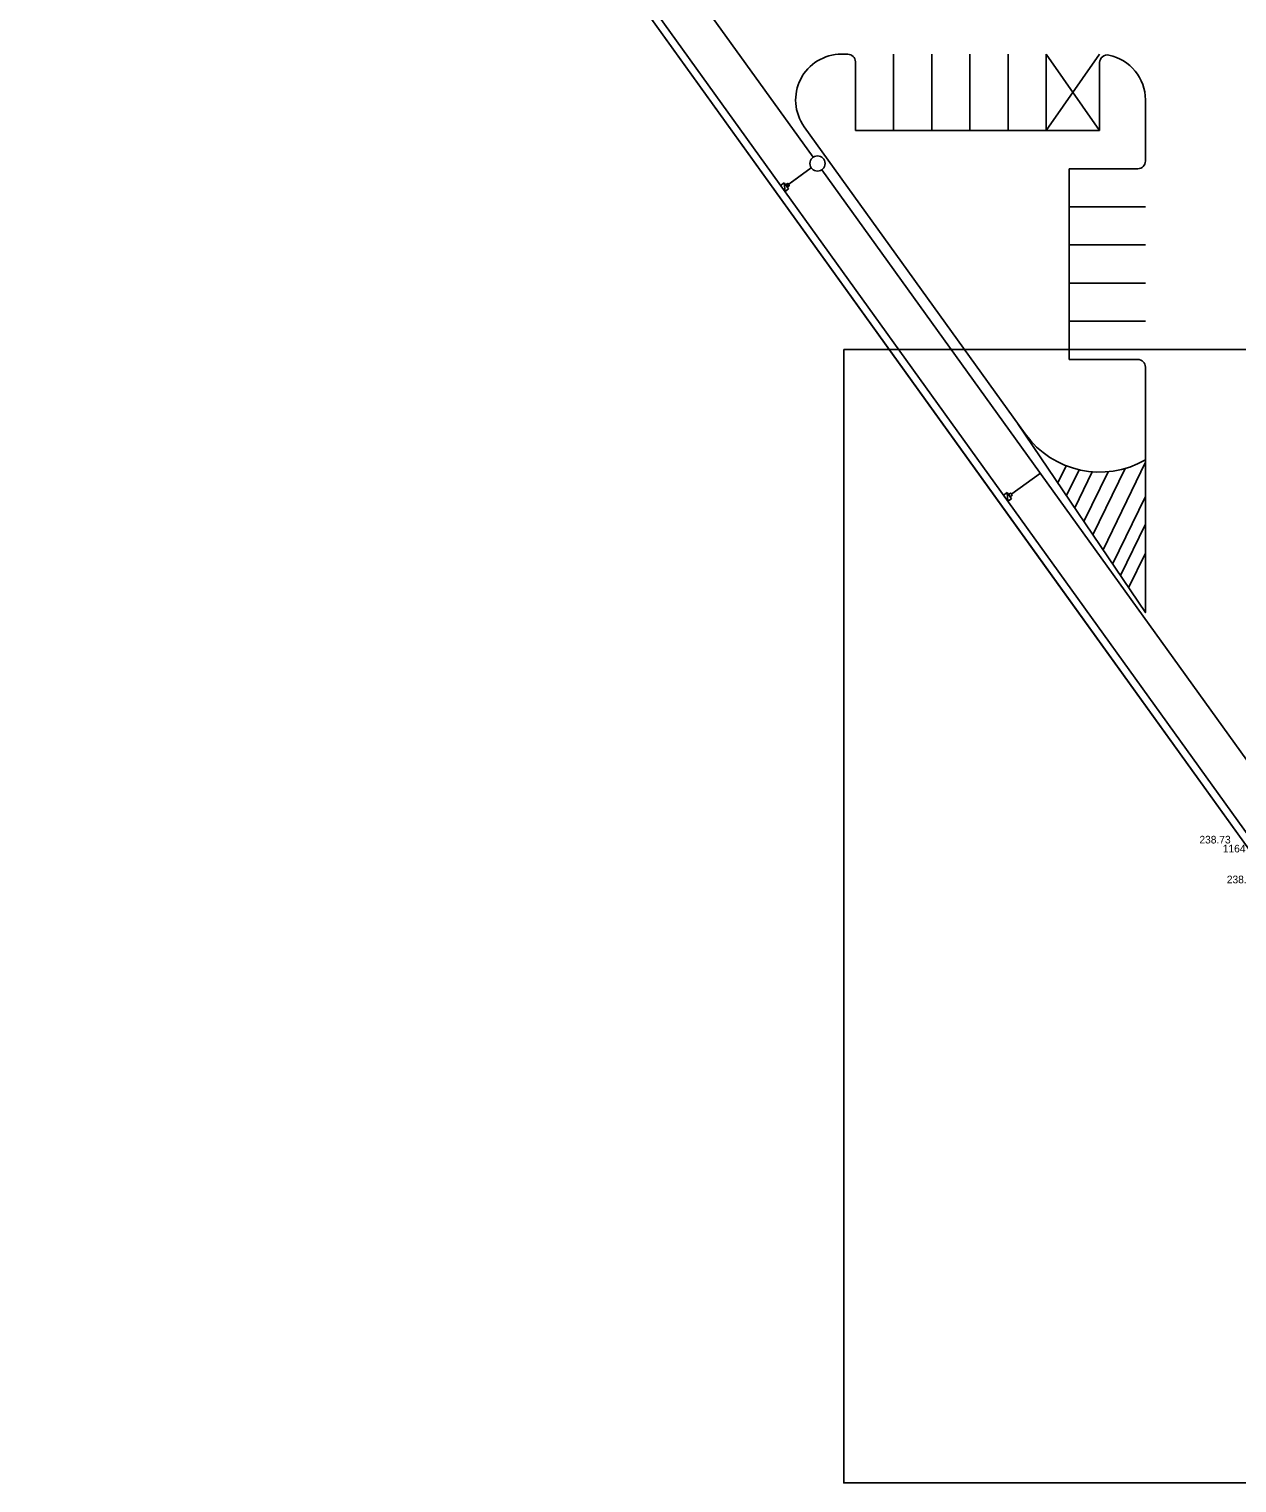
# Model space of a CAD drawing. Extents: x -264205 to -263615, y -1242401 to -1242031.
# Drawn here: x -264204.7 to -264125.6, y -1242344.1 to -1242248.8 of the extents above; entities that cross this region are included whole.
import ezdxf

# ---------------------------------------------------------------- set-up
doc = ezdxf.new("R2010")
doc.units = 0
for name, color, linetype in [('BODY_SYMBOL A CISLO_2-1', 7, 'Continuous'), ('BODY_VYSKA_2-1', 7, 'Continuous'), ('KOORDINACNA_SITUACIA_DSP', 7, 'Continuous'), ('PROJEKT_DRS_TDZ_VODOROVNE', 7, 'Continuous'), ('RAM_NA_TLAC_1-250_SITUACIA_2-1', 7, 'Continuous')]:
    doc.layers.add(name, color=color, linetype=linetype)

msp = doc.modelspace()

# ---------------------------------------------------------------- linework, layer by layer
at = {"layer": 'KOORDINACNA_SITUACIA_DSP'}
for p, q in [((-264204.694, -1242191.482), (-264115.871, -1242314.982)), ((-264204.078, -1242191.482), (-264119.75, -1242308.732)), ((-264181.951, -1242217.458), (-264153.34, -1242257.238)), ((-264151.48, -1242250.482), (-264151.068, -1242250.482)), ((-264150.568, -1242255.482), (-264150.568, -1242250.982)), ((-264134.568, -1242255.482), (-264134.568, -1242251.033)), ((-264131.568, -1242257.482), (-264131.568, -1242253.482)), ((-264153.916, -1242255.234), (-264139.439, -1242275.363)), ((-264150.568, -1242255.482), (-264134.568, -1242255.482)), ((-264155.084, -1242259.108), (-264153.454, -1242257.936)), ((-264154.921, -1242258.991), (-264153.454, -1242257.936)), ((-264136.568, -1242257.982), (-264136.568, -1242270.482)), ((-264136.568, -1242257.982), (-264132.068, -1242257.982)), ((-264155.465, -1242259.074), (-264155.23, -1242258.905)), ((-264155.23, -1242258.905), (-264154.938, -1242259.311)), ((-264155.23, -1242258.905), (-264155.173, -1242259.48)), ((-264155.23, -1242258.905), (-264155.173, -1242259.48)), ((-264154.938, -1242259.311), (-264155.23, -1242258.905)), ((-264152.757, -1242258.05), (-264124.146, -1242297.83)), ((-264152.757, -1242258.05), (-264124.146, -1242297.83)), ((-264155.173, -1242259.48), (-264155.465, -1242259.074)), ((-264154.938, -1242259.311), (-264155.173, -1242259.48)), ((-264155.173, -1242259.48), (-264154.938, -1242259.311)), ((-264136.568, -1242270.482), (-264132.068, -1242270.482)), ((-264131.568, -1242270.982), (-264131.568, -1242277.056)), ((-264140.324, -1242279.287), (-264138.451, -1242277.94)), ((-264140.868, -1242279.37), (-264140.632, -1242279.201)), ((-264140.576, -1242279.776), (-264140.868, -1242279.37)), ((-264140.632, -1242279.201), (-264140.341, -1242279.607)), ((-264140.632, -1242279.201), (-264140.576, -1242279.776)), ((-264140.632, -1242279.201), (-264140.576, -1242279.776)), ((-264140.341, -1242279.607), (-264140.632, -1242279.201)), ((-264140.341, -1242279.607), (-264140.576, -1242279.776)), ((-264140.576, -1242279.776), (-264140.341, -1242279.607))]:
    msp.add_line(p, q, dxfattribs=at)
msp.add_lwpolyline([(-264204.694, -1242191.482), (-264137.78, -1242284.52), (-264125.581, -1242301.482)], dxfattribs=at)
for centre, radius in [((-264153.049, -1242257.644), 0.5), ((-264155, -1242259.053), 0.1), ((-264140.403, -1242279.349), 0.1)]:
    msp.add_circle(centre, radius, dxfattribs=at)
for centre, radius, start, end in [((-264151.48, -1242253.482), 3, 90, 215.72401), ((-264151.068, -1242250.982), 0.5, 0, 90), ((-264134.068, -1242251.033), 0.5, 78.46304, 180), ((-264134.568, -1242253.482), 3, 0, 78.46304), ((-264132.068, -1242257.482), 0.5, 270, 0), ((-264132.068, -1242270.982), 0.5, 0, 90), ((-264134.568, -1242271.86), 6, 215.72401, 300)]:
    msp.add_arc(centre, radius, start, end, dxfattribs=at)
at = {"layer": 'PROJEKT_DRS_TDZ_VODOROVNE'}
for p, q in [((-264148.068, -1242255.482), (-264148.068, -1242250.482)), ((-264145.568, -1242255.482), (-264145.568, -1242250.482)), ((-264143.068, -1242255.482), (-264143.068, -1242250.482)), ((-264140.568, -1242255.482), (-264140.568, -1242250.482)), ((-264138.068, -1242255.482), (-264138.068, -1242250.482)), ((-264134.581, -1242250.484), (-264138.068, -1242255.482)), ((-264138.066, -1242250.484), (-264134.568, -1242255.482)), ((-264136.568, -1242260.482), (-264131.568, -1242260.482)), ((-264136.568, -1242262.982), (-264131.568, -1242262.982)), ((-264136.568, -1242265.482), (-264131.568, -1242265.482)), ((-264136.568, -1242267.982), (-264131.568, -1242267.982)), ((-264137.302, -1242278.57), (-264136.756, -1242277.446)), ((-264136.741, -1242279.401), (-264135.918, -1242277.706)), ((-264136.202, -1242280.199), (-264135.057, -1242277.84)), ((-264135.592, -1242281.102), (-264134.007, -1242277.833)), ((-264135.007, -1242281.969), (-264132.898, -1242277.623)), ((-264134.346, -1242282.947), (-264131.568, -1242277.22)), ((-264133.714, -1242283.883), (-264131.568, -1242279.459)), ((-264133.202, -1242284.642), (-264131.568, -1242281.274)), ((-264132.667, -1242285.434), (-264131.568, -1242283.169))]:
    msp.add_line(p, q, dxfattribs=at)
msp.add_lwpolyline([(-264139.918, -1242274.696), (-264131.568, -1242287.061), (-264131.568, -1242277.056)], dxfattribs=at)
at = {"layer": 'RAM_NA_TLAC_1-250_SITUACIA_2-1'}
msp.add_lwpolyline([(-264151.333, -1242269.835), (-263718.833, -1242269.835), (-263718.833, -1242344.085), (-264151.333, -1242344.085)], close=True, dxfattribs=at)

# ---------------------------------------------------------------- texts
at = {"layer": 'BODY_SYMBOL A CISLO_2-1'}
msp.add_text('1164', height=0.5, dxfattribs=at).set_placement((-264126.499, -1242302.777))
at = {"layer": 'BODY_VYSKA_2-1'}
for s, p in [('238.73', (-264128.03, -1242302.191)), ('238.74', (-264126.236, -1242304.8))]:
    msp.add_text(s, height=0.5, dxfattribs=at).set_placement(p)

doc.saveas('drawing.dxf')
